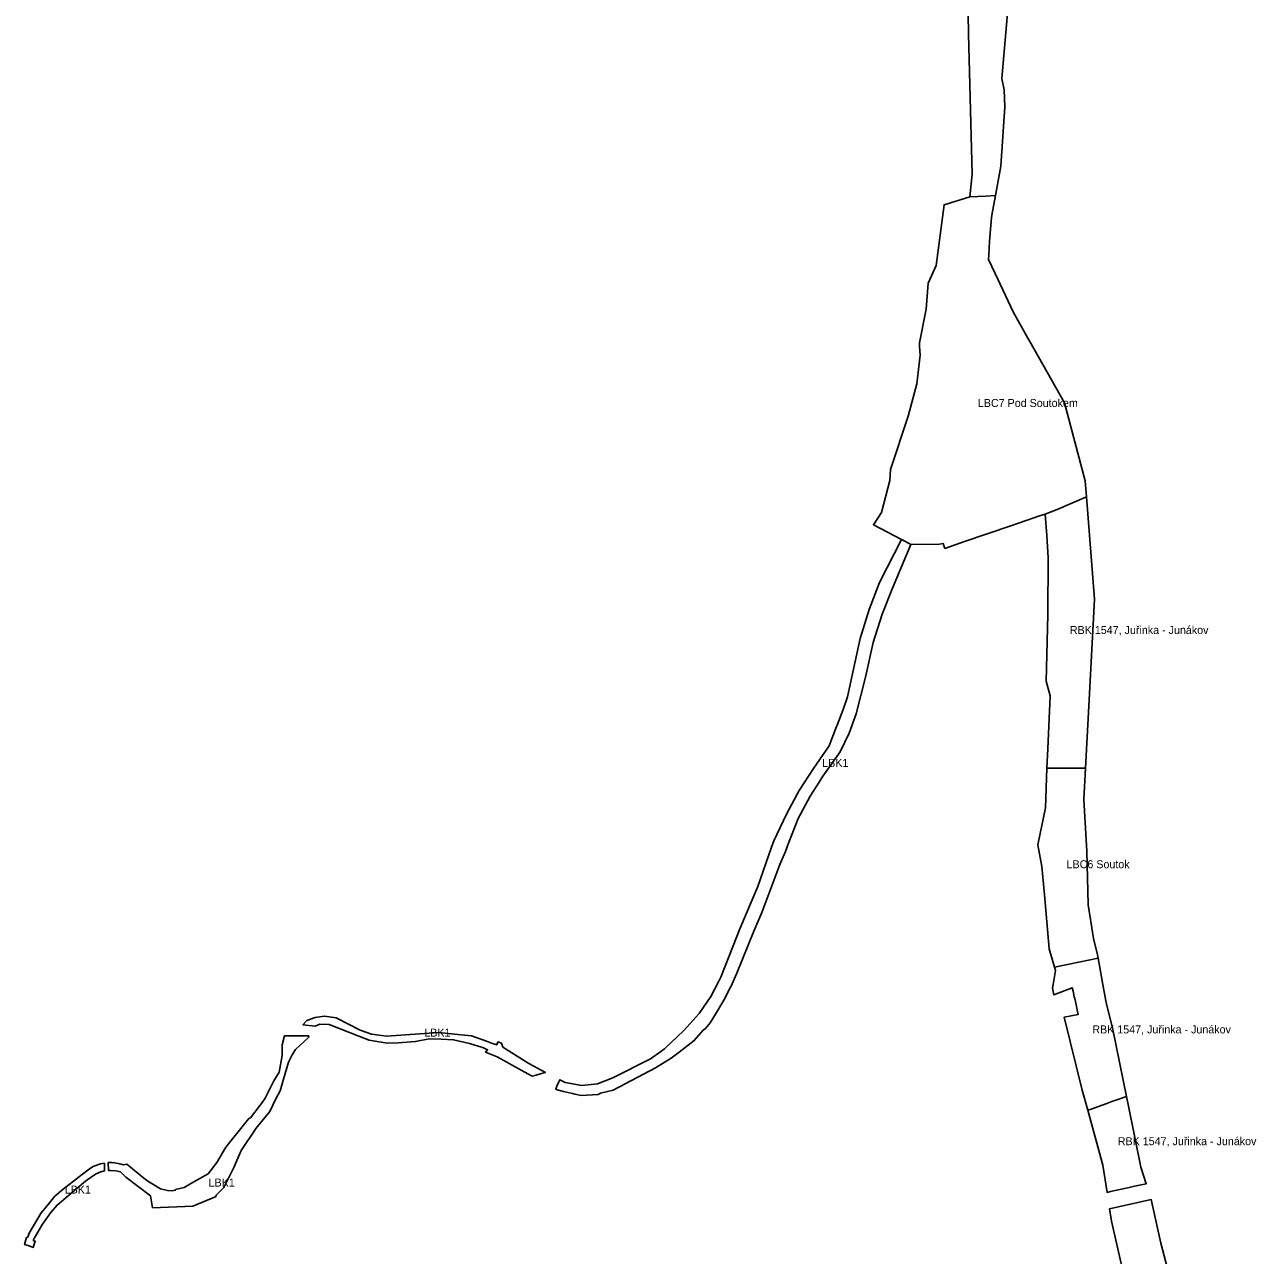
# Model space of a CAD drawing. Extents: x -502026 to -497556, y -1143322 to -1138019.
# Drawn here: x -498823 to -497592, y -1140479 to -1139249 of the extents above; entities that cross this region are included whole.
import ezdxf

# ---------------------------------------------------------------- set-up
doc = ezdxf.new("R2010")
doc.units = 0
for name, color, linetype in [('13', 7, 'Continuous'), ('14', 7, 'Continuous'), ('16', 7, 'Continuous'), ('19', 7, 'Continuous')]:
    doc.layers.add(name, color=color, linetype=linetype)

msp = doc.modelspace()

# ---------------------------------------------------------------- linework, layer by layer
at = {"layer": '13'}
msp.add_lwpolyline([(-497838.59, -1139210.88), (-497846.62, -1139303.16), (-497844.4, -1139314.38), (-497843.73, -1139331.53), (-497847.64, -1139390.66), (-497853.045, -1139419.975), (-497862.54, -1139420.505), (-497878.58, -1139421.4), (-497876.35, -1139398.74), (-497880.04, -1139258.3), (-497881.28, -1139178.83)], dxfattribs=at)
for points in [[(-497763.167, -1139992.409), (-497801.583, -1139992.436), (-497800.8, -1139973.1), (-497798.43, -1139920.05), (-497802.42, -1139905.22), (-497800.8, -1139839.1), (-497800.42, -1139782.06), (-497801.75, -1139759.81), (-497803.397, -1139738.564), (-497791.283, -1139733.868), (-497762.167, -1139721.173), (-497754.15, -1139823.33), (-497759.51, -1139923.87)], [(-497738.052, -1140415.414), (-497741.556, -1140416.179), (-497745.87, -1140388.9), (-497760.746, -1140334.19), (-497757.255, -1140332.936), (-497741.761, -1140327.373), (-497736.638, -1140325.534), (-497733.802, -1140324.516), (-497722.038, -1140320.293), (-497720.378, -1140328.482), (-497707.7, -1140391.05), (-497702.315, -1140407.614), (-497714.01, -1140410.166), (-497719.331, -1140411.328)], [(-497664.79, -1140617.64), (-497663.84, -1140660.72), (-497663.83, -1140661.21), (-497664.59, -1140668.32), (-497683.37, -1140667.28), (-497691.84, -1140657.78), (-497695.17, -1140657.43), (-497703.28, -1140658.33), (-497704.11, -1140619.29), (-497708.97, -1140576.79), (-497712.04, -1140556.773), (-497722.062, -1140510.625), (-497736.978, -1140445.132), (-497738.975, -1140432.504), (-497710.808, -1140426.361), (-497697.403, -1140423.438), (-497687.61, -1140466.9), (-497679.11, -1140500), (-497668.31, -1140542.04), (-497664.47, -1140603.39)]]:
    msp.add_lwpolyline(points, close=True, dxfattribs=at)
at = {"layer": '14'}
msp.add_lwpolyline([(-497750.361, -1140182.123), (-497744.65, -1140214.23), (-497744.34, -1140215.94), (-497743.12, -1140222.81), (-497742.97, -1140223.61), (-497742.46, -1140226.49), (-497735.58, -1140253.46), (-497722.038, -1140320.293), (-497733.802, -1140324.516), (-497736.638, -1140325.534), (-497741.761, -1140327.373), (-497757.255, -1140332.936), (-497760.746, -1140334.19), (-497766.22, -1140314.06), (-497784.27, -1140241.09), (-497770.35, -1140238.29), (-497771.3, -1140234.04), (-497772.19, -1140230.04), (-497773.87, -1140222.54), (-497774.27, -1140220.73), (-497775.52, -1140215.16), (-497776.29, -1140211.71), (-497794.66, -1140218.96), (-497796.02, -1140211.8), (-497795.48, -1140208.51), (-497793.18, -1140194.54), (-497794.171, -1140191.113), (-497769.85, -1140186.122)], close=True, dxfattribs=at)
at = {"layer": '16'}
for points in [[(-497939.883, -1139767.469), (-497943.537, -1139765.549), (-497946.9, -1139763.783), (-497974.94, -1139749.05), (-497967.07, -1139736.73), (-497958.55, -1139704.66), (-497957.93, -1139693.75), (-497940.43, -1139640.6), (-497931.52, -1139608.34), (-497928.3, -1139579.61), (-497928.833, -1139570.983), (-497929.06, -1139567.32), (-497922.15, -1139533.52), (-497920.16, -1139507.56), (-497912.33, -1139490.05), (-497904.46, -1139429.18), (-497878.58, -1139421.4), (-497862.54, -1139420.505), (-497853.045, -1139419.975), (-497856.69, -1139439.74), (-497857.18, -1139445.63), (-497858.87, -1139465.8), (-497859.58, -1139479.18), (-497859.83, -1139483.92), (-497853.25, -1139498.03), (-497835.44, -1139536.2), (-497820.53, -1139562.64), (-497818.73, -1139565.84), (-497784.14, -1139627.18), (-497763.42, -1139705.21), (-497762.167, -1139721.173), (-497791.283, -1139733.868), (-497803.397, -1139738.564), (-497809.95, -1139740.28), (-497814.7, -1139741.95), (-497837.54, -1139749.94), (-497883.9, -1139765.85), (-497903.5, -1139772.63), (-497905.42, -1139767.64), (-497909.09, -1139768.28), (-497937.56, -1139768.69)], [(-497801.583, -1139992.436), (-497763.167, -1139992.409), (-497764.83, -1140023.57), (-497761.85, -1140075.33), (-497760.38, -1140128.92), (-497758.12, -1140143.41), (-497757.81, -1140145.41), (-497755.13, -1140162.59), (-497750.97, -1140178.7), (-497750.361, -1140182.123), (-497769.85, -1140186.122), (-497794.171, -1140191.113), (-497799.48, -1140172.76), (-497803.97, -1140118.97), (-497806.7, -1140090.71), (-497810.64, -1140069), (-497803.18, -1140031.89)]]:
    msp.add_lwpolyline(points, close=True, dxfattribs=at)
at = {"layer": '19'}
for points in [[(-498192.83, -1140291.71), (-498235.15, -1140314.06), (-498240.77, -1140315.36), (-498247.78, -1140316.98), (-498250.06, -1140318.42), (-498267.08, -1140319.56), (-498273.4, -1140318.03), (-498275.58, -1140317.5), (-498284.66, -1140315.3), (-498291.06, -1140313.88), (-498292.56, -1140313.09), (-498291.29, -1140310.21), (-498289.64, -1140306.45), (-498288.43, -1140303.7), (-498283.1, -1140306.27), (-498266.58, -1140309.38), (-498250.87, -1140307.86), (-498235.28, -1140301.81), (-498197.77, -1140282.61), (-498187.37, -1140275.36), (-498183.78, -1140272.87), (-498164.48, -1140254.47), (-498149.3, -1140237.45), (-498137.41, -1140220.42), (-498129.511, -1140204.996), (-498127.49, -1140201.05), (-498115.098, -1140169.861), (-498108.39, -1140152.98), (-498090.56, -1140110.67), (-498076.9, -1140071.11), (-498074.46, -1140064.99), (-498061.7, -1140037.59), (-498049.31, -1140014.76), (-498035.04, -1139992.75), (-498019.07, -1139969.8), (-498011.9, -1139950.71), (-498011.32, -1139949.27), (-498005.08, -1139933.72), (-498000.78, -1139920.93), (-497994.884, -1139893.368), (-497988.34, -1139862.78), (-497979.28, -1139833.6), (-497968.84, -1139806.79), (-497946.9, -1139763.783), (-497943.537, -1139765.549), (-497939.883, -1139767.469), (-497937.56, -1139768.69), (-497955.99, -1139812.55), (-497966.39, -1139838.27), (-497975.41, -1139866.55), (-497982.83, -1139901.29), (-497992.15, -1139937.92), (-497999.1, -1139957.15), (-498008.36, -1139976.05), (-498025.48, -1140000.43), (-498029.291, -1140006.395), (-498038.13, -1140020.23), (-498050.2, -1140042.69), (-498059.95, -1140067.22), (-498062.98, -1140075.71), (-498068.59, -1140088.62), (-498078.48, -1140115.11), (-498086.46, -1140136.48), (-498094.6, -1140155.29), (-498100.22, -1140169.17), (-498105.78, -1140183.21), (-498111.53, -1140197.11), (-498117.56, -1140210.67), (-498117.81, -1140211.166), (-498124.37, -1140224.17), (-498132.85, -1140238.27), (-498138.3, -1140246.91), (-498142.87, -1140252.35), (-498145.2, -1140254.17), (-498154, -1140264.6), (-498169.24, -1140276.07), (-498177.05, -1140282.16)], [(-498512.04, -1140241.67), (-498488.09, -1140253.97), (-498476.48, -1140258.14), (-498461.5, -1140260.09), (-498409.49, -1140256.52), (-498393.76, -1140257.98), (-498376.71, -1140259.93), (-498361.68, -1140265.12), (-498356.78, -1140267.13), (-498351.49, -1140268.8), (-498350.3, -1140265.88), (-498346.59, -1140267.1), (-498345.41, -1140271.07), (-498319.48, -1140287.27), (-498302.78, -1140296.403), (-498306.733, -1140297.525), (-498312.163, -1140299.065), (-498316.108, -1140300.184), (-498324.07, -1140295.85), (-498327.19, -1140294.11), (-498339.05, -1140287.49), (-498341.53, -1140286.11), (-498350.98, -1140280.84), (-498362.603, -1140275.986), (-498360.57, -1140273.73), (-498365.5, -1140271.49), (-498370.07, -1140270.05), (-498378.71, -1140267.34), (-498394.74, -1140263.63), (-498407, -1140263.15), (-498418.98, -1140262.69), (-498432.81, -1140265.27), (-498449.89, -1140266.73), (-498460.91, -1140267.15), (-498478.83, -1140264.15), (-498489.252, -1140260.062), (-498518.98, -1140248.4), (-498528.28, -1140247.99), (-498533.03, -1140250.13), (-498545.22, -1140248.67), (-498541.15, -1140244.61), (-498532.76, -1140241.54), (-498523.57, -1140240.06)], [(-498695.57, -1140431.55), (-498697.49, -1140419.56), (-498722.04, -1140400.93), (-498727.49, -1140395.85), (-498732.26, -1140394.64), (-498737.19, -1140394.36), (-498739.51, -1140394.23), (-498739.75, -1140386.38), (-498737.7, -1140386.43), (-498735.97, -1140386.48), (-498733.35, -1140386.55), (-498728.2, -1140387.65), (-498724.52, -1140388.76), (-498721.27, -1140388.18), (-498703.99, -1140401.95), (-498700.27, -1140404.92), (-498687.52, -1140412.83), (-498680.66, -1140414.32), (-498675.89, -1140414.61), (-498672.83, -1140414.11), (-498672.4, -1140413.46), (-498664, -1140411.21), (-498662.268, -1140410.261), (-498654.04, -1140405.75), (-498639.83, -1140397.65), (-498634.32, -1140390.23), (-498630.63, -1140385.27), (-498623.34, -1140372.65), (-498620.83, -1140369.5), (-498601.88, -1140345.827), (-498598.8, -1140341.98), (-498597.43, -1140341.87), (-498587.81, -1140329.06), (-498586.54, -1140327.36), (-498582.98, -1140321.99), (-498574.07, -1140304.58), (-498568.811, -1140295.953), (-498565.894, -1140279.424), (-498565.96, -1140268.7), (-498563.73, -1140259.82), (-498539.34, -1140259.87), (-498539.49, -1140261.53), (-498552.66, -1140273.5), (-498555.99, -1140278.71), (-498559.51, -1140286.19), (-498564.44, -1140303.13), (-498567.78, -1140314.8), (-498572.23, -1140322.83), (-498578.18, -1140335.35), (-498592.134, -1140352.318), (-498592.67, -1140352.97), (-498606.78, -1140374.21), (-498614.09, -1140391.2), (-498624.28, -1140411.45), (-498632.31, -1140419.2), (-498631.97, -1140420.41), (-498655.07, -1140430.02)], [(-498762.37, -1140405.04), (-498764.36, -1140406.72), (-498790.77, -1140428.9), (-498797.14, -1140436.32), (-498798.911, -1140438.777), (-498805.54, -1140447.97), (-498813.3, -1140461.48), (-498814.61, -1140464.19), (-498812.74, -1140465.05), (-498814.8, -1140471.18), (-498818.81, -1140469.76), (-498823.28, -1140468.41), (-498821.38, -1140461.18), (-498820.01, -1140460.85), (-498818.79, -1140457.08), (-498806.74, -1140436.78), (-498801.212, -1140429.991), (-498799.9, -1140428.38), (-498793.01, -1140419.91), (-498784.7, -1140413.15), (-498768.37, -1140400.19), (-498766.7, -1140398.86), (-498757.58, -1140391.94), (-498754.71, -1140390.44), (-498752.1, -1140389.47), (-498747.39, -1140387.71), (-498743.53, -1140387.04), (-498743.556, -1140394.77), (-498747.2, -1140395.62), (-498751.71, -1140397.67), (-498754.41, -1140399.29)]]:
    msp.add_lwpolyline(points, close=True, dxfattribs=at)

# ---------------------------------------------------------------- texts
at = {"layer": '13'}
for p in [(-497778.698, -1139858.211), (-497730.799, -1140369.051)]:
    msp.add_text('RBK 1547, Juřinka - Junákov', height=8, dxfattribs=at).set_placement(p)
at = {"layer": '14'}
msp.add_text('RBK 1547, Juřinka - Junákov', height=8, dxfattribs=at).set_placement((-497756.25, -1140257.362))
at = {"layer": '16'}
for s, p in [('LBC7 Pod Soutokem', (-497870.639, -1139631.335)), ('LBC6 Soutok', (-497781.971, -1140092.297))]:
    msp.add_text(s, height=8, dxfattribs=at).set_placement(p)
at = {"layer": '19'}
for p in [(-498026.168, -1139990.961), (-498423.859, -1140260.565), (-498639.404, -1140410.408), (-498783.264, -1140417.413)]:
    msp.add_text('LBK1', height=8, dxfattribs=at).set_placement(p)

doc.saveas('drawing.dxf')
